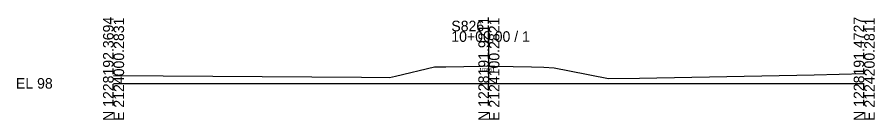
# Model space of a CAD drawing. Extents: x 2118382 to 2118616, y 1213030 to 1222057.
# Drawn here: x 2118381.9 to 2118610.4, y 1220530.1 to 1220557.4 of the extents above; entities that cross this region are included whole.
import ezdxf

# ---------------------------------------------------------------- set-up
doc = ezdxf.new("R2010")
doc.units = 0
for name, color, linetype in [('XS_CELL', 7, 'Continuous'), ('XS_X_GROUND', 7, 'Continuous'), ('XS_X_GROUND_TX', 7, 'Continuous')]:
    doc.layers.add(name, color=color, linetype=linetype)

msp = doc.modelspace()

# ---------------------------------------------------------------- linework, layer by layer
at = {"layer": 'XS_CELL'}
for p, q in [((2118507.6, 1220539.8), (2118507.6, 1220553.64)), ((2118407.6, 1220539.8), (2118507.6, 1220539.8)), ((2118507.6, 1220539.8), (2118607.6, 1220539.8))]:
    msp.add_line(p, q, dxfattribs=at)
at = {"layer": 'XS_X_GROUND'}
for p, q in [((2118482.72, 1220541.75), (2118493.15, 1220544.15)), ((2118493.15, 1220544.15), (2118493.93, 1220544.17)), ((2118493.93, 1220544.17), (2118496.09, 1220544.22)), ((2118496.09, 1220544.22), (2118505.75, 1220544.4)), ((2118505.75, 1220544.4), (2118507.21, 1220544.42)), ((2118507.21, 1220544.42), (2118507.6, 1220544.41)), ((2118507.6, 1220544.41), (2118509.2, 1220544.38)), ((2118509.2, 1220544.38), (2118518.94, 1220544.21)), ((2118518.94, 1220544.21), (2118522.27, 1220544.06)), ((2118522.27, 1220544.06), (2118525.03, 1220543.96)), ((2118525.03, 1220543.96), (2118529.07, 1220543.15)), ((2118529.07, 1220543.15), (2118539.5, 1220541.05)), ((2118594.27, 1220542.08), (2118607.6, 1220542.45)), ((2118407.6, 1220541.9), (2118473.69, 1220541.45)), ((2118473.69, 1220541.45), (2118481.08, 1220541.39)), ((2118481.08, 1220541.39), (2118482.72, 1220541.75)), ((2118539.5, 1220541.05), (2118547.76, 1220541.19)), ((2118547.76, 1220541.19), (2118594.27, 1220542.08))]:
    msp.add_line(p, q, dxfattribs=at)

# ---------------------------------------------------------------- texts
at = {"layer": 'XS_CELL'}
for s, p in [('N 1228192.3694', (2118407.6, 1220529.8)), ('E 2124000.2831', (2118410.4, 1220529.8)), ('N 1228191.9211', (2118507.6, 1220529.8)), ('E 2124100.2821', (2118510.4, 1220529.8)), ('N 1228191.4727', (2118607.6, 1220529.8)), ('E 2124200.2811', (2118610.4, 1220529.8))]:
    msp.add_text(s, height=2.8, rotation=90, dxfattribs=at).set_placement(p)
for s, p in [('S826', (2118497.6, 1220553.64)), ('10+00.00 / 1', (2118497.6, 1220550.84)), ('EL 98', (2118381.6, 1220538.4))]:
    msp.add_text(s, height=2.8, dxfattribs=at).set_placement(p)
at = {"layer": 'XS_X_GROUND_TX'}
msp.add_text('102.61', height=1, dxfattribs=at).set_placement((2118505, 1220542.91))

doc.saveas('drawing.dxf')
